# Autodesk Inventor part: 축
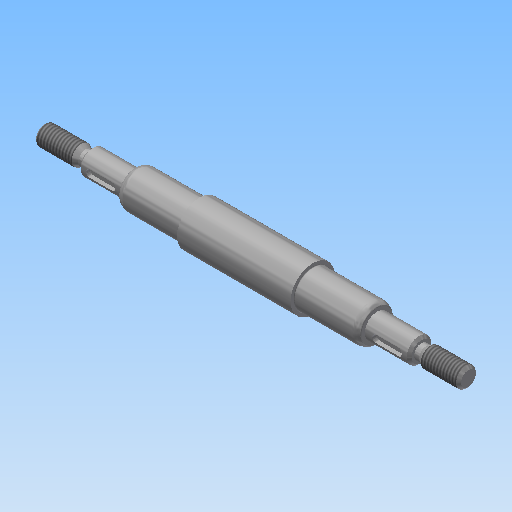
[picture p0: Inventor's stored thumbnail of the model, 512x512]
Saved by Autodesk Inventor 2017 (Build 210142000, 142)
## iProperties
Created: 2015-11
Part Number: 축
Material: 강철, 연강
Document SubType Name: Modeling
Designer: mduedu
Density: 7.86 g/cm^3
Mass: 198.507 g
Surface Area: 75.8873 cm^2
Volume: 25.2553 cm^3
Appearance: 강철
Author: mduedu
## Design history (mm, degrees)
sketch "스케치1"
  geometry: L1 (-86, 0)-(86, 0); L2 (-86, 0)-(-86, 4); L3 (-86, 4)-(-70.732, 4); L4 (-70.732, 4)-(-69, 3); L5 (-69, 3)-(-67, 3); L6 (-67, 3)-(-67, 5); L7 (-67, 5)-(-49, 5); L8 (-49, 5)-(-49, 6.55); L9 (-47.355, 7.5)-(-23, 7.5); L10 (-23, 7.5)-(-23, 9); L11 (0, 0)-(0, 9); L12 (86, 4)-(70.732, 4); L13 (70.732, 4)-(69, 3); L14 (69, 3)-(67, 3); L15 (67, 3)-(67, 5); L16 (67, 5)-(49, 5); L17 (23, 7.5)-(23, 9); L18 (86, 0)-(86, 4); L19 (-23, 9)-(23, 9); L20 (-49, 6.55)-(-47.355, 7.5); L21 (47.355, 7.5)-(23, 7.5); L22 (49, 6.55)-(47.355, 7.5); L23 (49, 5)-(49, 6.55); 1 further point
  constraints: 46 end point, 10 symmetric about line, 6 perpendicular, 5 parallel, 2 midpoint, 1 coincident, 1 horizontal
  dimensions: "d0" = 172 distance of L1.start L1.end (derived); "d1" = 8 diameter of L3 L1; "d2" = 30 deg angle of L4 L5; "d3" = 6 diameter of L5 L1; "d4" = 10 diameter of L7 L1; "d5" = 15 diameter of L9 L1; "d6" = 18 diameter of L19 L1; "d8" = 18 distance of L6.end L7.end; "d9" = 46 distance of L10.end L17.end; "d10" = 2 distance of L4.end L5.end; "d11" = 17 distance from line of L4.end L2; "d16" = 13.1 diameter of L8.end L1; "d17" = 30 deg angle of L20 L9; "d18" = 26 distance between parallel lines of L10 L8
revolve "회전1" sketch "스케치1" stored, may be unused: angle "d12" = 90 deg
chamfer "모따기1" distance "d13" = 1; stored, may be unused: second distance "d14" = 2, angle "d15" = 45 deg
fillet "모깎기1" dims "d19" = 4, "d20" = 0.5
node "작업 평면1"
sketch "스케치2" dims "d23" = 12
  geometry: L1 (-4.5, 1.5)-(4.5, 1.5); L2 (4.5, 1.5)-(4.5, -1.5); L3 (4.5, -1.5)-(-4.5, -1.5); L4 (-4.5, -1.5)-(-4.5, 1.5); L5 (-9, -4)-(-9, 4) reference; 3 further points
  constraints: 8 end point, 2 midpoint, 2 parallel, 2 vertical alignment, 1 horizontal, 1 perpendicular, 4 other
  dimensions: "d21" = 3 distance between parallel lines of L3 L1; "d24" = 3 dimension on L5
extrude "돌출1" cut sketch "스케치2" distance "d25" = 1.8; taper "d26" = 0 deg
feature "스레드1" dims "d27" = 10, "d28" = 0
feature "스레드2" dims "d29" = 10, "d30" = 0
chamfer "모따기2" distance "d31" = 1; stored, may be unused: second distance "d32" = 2, angle "d33" = 45 deg
fillet "모깎기2" dims "d34" = 0.3
node "솔리드1"
mirror "대칭1"
